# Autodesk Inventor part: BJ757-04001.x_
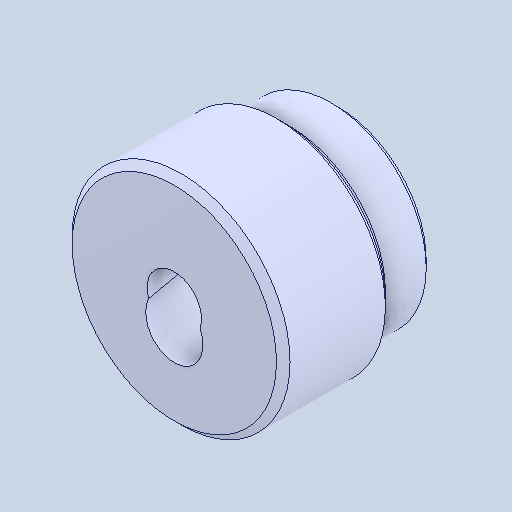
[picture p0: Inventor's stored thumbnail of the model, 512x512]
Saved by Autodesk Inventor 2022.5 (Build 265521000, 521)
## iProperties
Created: 2024-05
Part Number: BJ757-04001.x_
Material: 一般
Document SubType Name: Modeling
Designer: ImaoCorp
Density: 1 g/cm^3
Appearance: 既定
Author: ImaoCorp
Sending System: SOLIDWORKS 2022-2022290
MC: AMD64
MC_MODEL: Intel64 Family 6 Model 60 Stepping 3, GenuineIntel
OS: Windows_NT
FRU: Parasolid Version 33.1, build 260,  4-25-2022
FORMAT: text
GUISE: transmit
KEY: FILEBJ757-04001.x_t
DATE: Tue May 21 08:47:16 2024
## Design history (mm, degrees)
feature "Base1"
node "ソリッド1"
